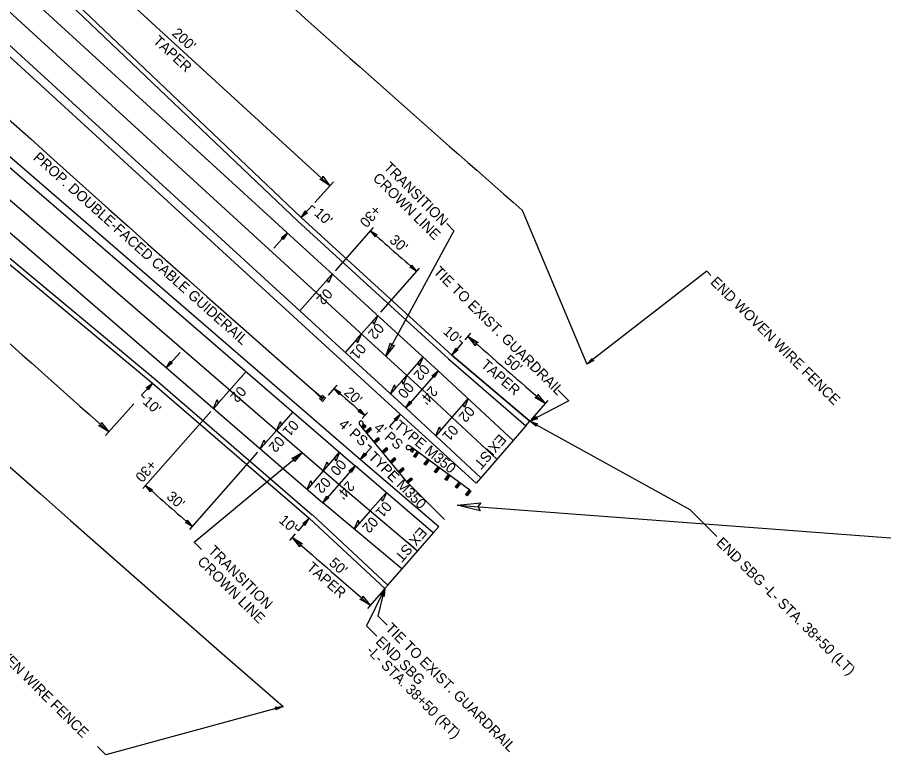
# Model space of a CAD drawing. Extents: x 1602193 to 1605074, y 908180 to 910630.
# Drawn here: x 1604022.9 to 1604444.5, y 908234.2 to 908593.2 of the extents above; entities that cross this region are included whole.
import ezdxf

# ---------------------------------------------------------------- set-up
doc = ezdxf.new("R2010")
doc.units = 0
for name, color, linetype in [('Prop Cable Guiderail Anchor Unit CELL', 7, 'Continuous'), ('Prop Cable Guiderail Double Face', 7, 'Continuous'), ('Prop Conc Shoulder Berm Gutter', 7, 'Continuous'), ('Prop Dimension', 7, 'Continuous'), ('Prop Dimension Text', 7, 'Continuous'), ('Prop DSN Text', 7, 'Continuous'), ('Prop EOT', 7, 'Continuous'), ('Prop Fence Woven Wire', 7, 'Continuous'), ('Prop Guardrail', 7, 'Continuous'), ('Prop Guardrail Anchor Unit CELL', 7, 'Continuous'), ('Prop Lane Lines', 7, 'Continuous'), ('Prop Paved Shoulder', 7, 'Continuous'), ('Prop Superelevation  Arrow CELL', 7, 'Continuous'), ('Prop Superelevation Label', 7, 'Continuous'), ('Prop Terminator CELL', 7, 'Continuous')]:
    doc.layers.add(name, color=color, linetype=linetype)

msp = doc.modelspace()

# ---------------------------------------------------------------- linework, layer by layer
at = {"layer": 'Prop Cable Guiderail Anchor Unit CELL'}
for p, q in [((1604153.38, 908423.5), (1604165.38, 908412.93)), ((1604165.38, 908412.93), (1604171.38, 908407.64)), ((1604165.38, 908412.93), (1604171.51, 908407.78)), ((1604165.38, 908412.93), (1604171.23, 908407.5)), ((1604165.38, 908412.93), (1604165.38, 908412.93)), ((1604171.29, 908409.05), (1604169.97, 908407.55)), ((1604171.47, 908406.23), (1604169.97, 908407.55)), ((1604171.47, 908408.12), (1604170.92, 908407.49)), ((1604171.3, 908407.16), (1604170.92, 908407.49)), ((1604172.8, 908407.73), (1604171.29, 908409.05)), ((1604171.85, 908407.78), (1604171.3, 908407.16)), ((1604171.85, 908407.78), (1604171.47, 908408.12)), ((1604172.8, 908407.73), (1604171.47, 908406.23))]:
    msp.add_line(p, q, dxfattribs=at)
at = {"layer": 'Prop Cable Guiderail Double Face'}
msp.add_arc((1613646.31, 919202), 14362.86, 225.366604, 228.628709, dxfattribs=at)
at = {"layer": 'Prop Conc Shoulder Berm Gutter'}
for p, q in [((1604016.5, 908633.39), (1604161.04, 908495.7)), ((1603934.31, 908543.23), (1604088.67, 908415.14)), ((1604161.04, 908495.7), (1604234.27, 908428.69)), ((1604234.27, 908428.69), (1604272.37, 908396.59)), ((1604088.67, 908415.14), (1604164.9, 908349.29)), ((1604270.42, 908394.34), (1604272.37, 908396.59)), ((1604164.9, 908349.29), (1604201.66, 908315.08)), ((1604201.66, 908315.08), (1604203.25, 908316.79))]:
    msp.add_line(p, q, dxfattribs=at)
at = {"layer": 'Prop Dimension'}
for p, q in [((1604027.95, 908645.82), (1604175.02, 908511.25)), ((1604176.72, 908513.15), (1604167.73, 908503.14)), ((1604161.04, 908495.7), (1604166.39, 908501.65)), ((1604196.08, 908490.81), (1604177.52, 908469.78)), ((1604231.84, 908492.85), (1604235.39, 908489.33)), ((1604147.68, 908480.82), (1604154.36, 908488.26)), ((1604235.39, 908489.33), (1604202.25, 908428.17)), ((1604218.48, 908471.09), (1604199.58, 908449.59)), ((1604240.85, 908436.22), (1604243.62, 908439.39)), ((1604234.46, 908428.9), (1604239.54, 908434.71)), ((1604095.35, 908422.58), (1604102.04, 908430.02)), ((1604227.69, 908421.16), (1604211.9, 908403.08)), ((1604083.32, 908409.19), (1604088.67, 908415.14)), ((1604178.34, 908414.05), (1604174.11, 908409.23)), ((1604281.1, 908406.65), (1604273.03, 908397.35)), ((1604079.55, 908404.99), (1604065.7, 908389.58)), ((1604117.03, 908401.22), (1604083.97, 908363.75)), ((1604193.37, 908400.87), (1604190.74, 908397.86)), ((1604209.26, 908400.06), (1604204, 908394.04)), ((1604139.8, 908381.54), (1604106.64, 908343.8)), ((1604108.99, 908337.66), (1604161.5, 908381.3)), ((1604187.27, 908374.89), (1604171.48, 908356.82)), ((1604159.64, 908343.26), (1604164.78, 908349.15)), ((1604155.46, 908338.48), (1604158.32, 908341.76)), ((1604112.55, 908334.14), (1604108.99, 908337.66)), ((1604201.01, 908314.33), (1604193.29, 908305.43))]:
    msp.add_line(p, q, dxfattribs=at)
for radius, start, end in [(14443.82, 227.66104, 228.45675), (14286.13, 228.578802, 228.698511), (14293.49, 228.858122, 229.057635), (14355.48, 228.728438, 228.808243), (14451.58, 228.578802, 228.698511), (14423.49, 228.858122, 229.057635)]:
    msp.add_arc((1613646.31, 919202), radius, start, end, dxfattribs=at)
at = {"layer": 'Prop Dimension Text'}
for p, q in [((1604166.39, 908501.65), (1604167.88, 908500.31)), ((1604238.03, 908436.03), (1604239.54, 908434.71)), ((1604083.32, 908409.19), (1604084.81, 908407.86)), ((1604204, 908394.04), (1604205.51, 908392.72)), ((1604193.66, 908385.24), (1604195.17, 908383.93)), ((1604195.17, 908383.93), (1604189.9, 908377.9)), ((1604158.13, 908344.58), (1604159.64, 908343.26))]:
    msp.add_line(p, q, dxfattribs=at)
at = {"layer": 'Prop DSN Text'}
for p, q in [((1604358.43, 908469.56), (1604300.01, 908424.29)), ((1604358.43, 908469.56), (1604360.47, 908467.54)), ((1604272.37, 908396.59), (1604350.11, 908353.55)), ((1604236.95, 908355.76), (1604508.97, 908335.15)), ((1604350.11, 908353.55), (1604363.29, 908340.51)), ((1604201.66, 908315.08), (1604192.77, 908296.9)), ((1604192.77, 908296.9), (1604197.84, 908291.88)), ((1604152.19, 908257.7), (1604065.86, 908234.2)), ((1604061.83, 908238.18), (1604065.86, 908234.2))]:
    msp.add_line(p, q, dxfattribs=at)
for points in [[(1604171.48, 908515.84), (1604175.02, 908511.25), (1604170.13, 908514.36), (1604171.32, 908514.63)], [(1604164.08, 908498.08), (1604161.04, 908495.7), (1604163.09, 908498.97), (1604163.27, 908498.18)], [(1604151.32, 908485.88), (1604154.36, 908488.26), (1604152.31, 908484.98), (1604152.13, 908485.78)], [(1604197.16, 908486.3), (1604194.75, 908489.31), (1604198.05, 908487.3), (1604197.25, 908487.1)], [(1604214.74, 908472.6), (1604217.16, 908469.59), (1604213.86, 908471.6), (1604214.65, 908471.79)], [(1604245.88, 908433.31), (1604242.25, 908437.82), (1604247.2, 908434.82), (1604246.01, 908434.53)], [(1604237.46, 908431.33), (1604234.46, 908428.9), (1604236.46, 908432.21), (1604236.65, 908431.42)], [(1604098.39, 908424.97), (1604095.35, 908422.58), (1604097.4, 908425.86), (1604097.58, 908425.06)], [(1604303.42, 908426.09), (1604300.01, 908424.29), (1604302.6, 908427.15), (1604302.64, 908426.33)], [(1604224.69, 908418.73), (1604227.69, 908421.16), (1604225.69, 908417.85), (1604225.5, 908418.64)], [(1604085.63, 908412.76), (1604088.67, 908415.14), (1604086.62, 908411.87), (1604086.44, 908412.66)], [(1604179.44, 908409.53), (1604177.02, 908412.54), (1604180.32, 908410.54), (1604179.53, 908410.34)], [(1604214.9, 908405.5), (1604211.9, 908403.08), (1604213.9, 908406.38), (1604214.09, 908405.59)], [(1604276.13, 908409.63), (1604279.79, 908405.14), (1604274.82, 908408.12), (1604276.01, 908408.41)], [(1604189.64, 908402.37), (1604192.06, 908399.36), (1604188.76, 908401.37), (1604189.55, 908401.56)], [(1604206.26, 908397.64), (1604209.26, 908400.06), (1604207.26, 908396.76), (1604207.07, 908397.55)], [(1604276.06, 908397.75), (1604272.37, 908396.59), (1604275.44, 908398.94), (1604275.33, 908398.13)], [(1604063.77, 908395.97), (1604067.38, 908391.44), (1604062.44, 908394.48), (1604063.63, 908394.76)], [(1604275.38, 908394.17), (1604272.37, 908396.59), (1604276.02, 908395.33), (1604275.29, 908394.98)], [(1604156.47, 908378.42), (1604161.5, 908381.3), (1604157.75, 908376.89), (1604157.65, 908378.1)], [(1604192.91, 908380.33), (1604189.9, 908377.9), (1604191.9, 908381.21), (1604192.1, 908380.42)], [(1604184.27, 908372.47), (1604187.27, 908374.89), (1604185.27, 908371.59), (1604185.08, 908372.38)], [(1604087.71, 908362.23), (1604085.3, 908365.25), (1604088.59, 908363.23), (1604087.8, 908363.04)], [(1604174.49, 908359.24), (1604171.48, 908356.82), (1604173.48, 908360.12), (1604173.68, 908359.33)], [(1604248.17, 908352.9), (1604236.95, 908355.76), (1604248.48, 908356.89), (1604246.93, 908355)], [(1604105.54, 908348.31), (1604107.96, 908345.3), (1604104.66, 908347.31), (1604105.45, 908347.5)], [(1604161.78, 908346.73), (1604164.78, 908349.15), (1604162.78, 908345.85), (1604162.59, 908346.64)], [(1604160.36, 908335.42), (1604156.72, 908339.92), (1604161.67, 908336.92), (1604160.49, 908336.63)], [(1604199.39, 908311.96), (1604201.66, 908315.08), (1604200.59, 908311.38), (1604200.2, 908312.09)], [(1604200.12, 908311.54), (1604201.66, 908315.08), (1604201.42, 908311.23), (1604200.88, 908311.84)], [(1604190.95, 908311.44), (1604194.6, 908306.94), (1604189.64, 908309.92), (1604190.82, 908310.22)], [(1604148.34, 908257.34), (1604152.19, 908257.7), (1604148.69, 908256.06), (1604148.97, 908256.82)]]:
    msp.add_lwpolyline(points, close=True, dxfattribs=at)
at = {"layer": 'Prop EOT'}
for p, q in [((1604007.07, 908623.04), (1604227.69, 908421.16)), ((1603990.88, 908605.32), (1604211.9, 908403.08)), ((1603959.9, 908571.31), (1604187.27, 908374.89)), ((1603943.97, 908553.36), (1604171.48, 908356.82)), ((1604264.18, 908387.15), (1604227.69, 908421.16)), ((1604248.45, 908369.01), (1604211.9, 908403.08)), ((1604264.18, 908387.15), (1604248.45, 908369.01)), ((1604225.27, 908342.29), (1604187.27, 908374.89)), ((1604209.93, 908324.61), (1604171.48, 908356.82)), ((1604225.27, 908342.29), (1604209.93, 908324.61))]:
    msp.add_line(p, q, dxfattribs=at)
at = {"layer": 'Prop Fence Woven Wire'}
msp.add_line((1604268.56, 908499.37), (1604300.01, 908424.29), dxfattribs=at)
for centre, radius, start, end in [((1613603.09, 919154.06), 14423.95, 224.073496, 229.063445), ((1613600.28, 919154.72), 14163.95, 227.268962, 228.788844)]:
    msp.add_arc(centre, radius, start, end, dxfattribs=at)
at = {"layer": 'Prop Guardrail'}
for p, q in [((1604161.04, 908495.7), (1604016.5, 908633.39)), ((1603934.31, 908543.23), (1604088.67, 908415.14)), ((1604234.27, 908428.69), (1604161.04, 908495.7)), ((1604272.37, 908396.59), (1604234.27, 908428.69)), ((1604088.67, 908415.14), (1604164.9, 908349.29)), ((1604230.85, 908348.73), (1604212.53, 908366.82)), ((1604164.9, 908349.29), (1604201.66, 908315.08))]:
    msp.add_line(p, q, dxfattribs=at)
at = {"layer": 'Prop Guardrail Anchor Unit CELL'}
for p, q in [((1604286.1, 908411.66), (1604291.37, 908406.45)), ((1604291.37, 908406.45), (1604272.37, 908396.59)), ((1604190.79, 908393.38), (1604189.4, 908395.08)), ((1604190.35, 908393.92), (1604191.6, 908394.95)), ((1604190.35, 908393.92), (1604190.9, 908394.37)), ((1604190.35, 908393.92), (1604190.9, 908394.37)), ((1604190.35, 908393.92), (1604192.49, 908393.86)), ((1604190.79, 908393.38), (1604191.43, 908393.91)), ((1604191.13, 908395.47), (1604190.9, 908394.37)), ((1604191.24, 908392.84), (1604191.6, 908394.95)), ((1604192.49, 908393.86), (1604191.24, 908392.84)), ((1604191.6, 908394.95), (1604192.49, 908393.86)), ((1604212.53, 908366.82), (1604190.79, 908393.38)), ((1604192.26, 908391.59), (1604194.54, 908393.45)), ((1604194.06, 908391.76), (1604192.26, 908391.59)), ((1604192.58, 908391.2), (1604193.16, 908391.68)), ((1604192.9, 908390.82), (1604195.17, 908392.68)), ((1604192.9, 908390.82), (1604193.42, 908392.54)), ((1604193.42, 908392.54), (1604195.17, 908392.68)), ((1604194.06, 908391.76), (1604193.42, 908392.54)), ((1604194.54, 908393.45), (1604194.06, 908391.76)), ((1604195.17, 908392.68), (1604194.54, 908393.45)), ((1604196.25, 908386.71), (1604198.53, 908388.57)), ((1604198.05, 908386.89), (1604196.25, 908386.71)), ((1604196.89, 908385.94), (1604199.16, 908387.8)), ((1604196.89, 908385.94), (1604197.41, 908387.66)), ((1604197.41, 908387.66), (1604199.16, 908387.8)), ((1604198.05, 908386.89), (1604197.41, 908387.66)), ((1604198.53, 908388.57), (1604198.05, 908386.89)), ((1604199.16, 908387.8), (1604198.53, 908388.57)), ((1604200.24, 908381.84), (1604202.52, 908383.7)), ((1604202.04, 908382.01), (1604200.24, 908381.84)), ((1604200.87, 908381.06), (1604203.15, 908382.92)), ((1604200.87, 908381.06), (1604201.4, 908382.79)), ((1604201.4, 908382.79), (1604203.15, 908382.92)), ((1604202.04, 908382.01), (1604201.4, 908382.79)), ((1604202.52, 908383.7), (1604202.04, 908382.01)), ((1604203.15, 908382.92), (1604202.52, 908383.7)), ((1604213.46, 908382.84), (1604214.54, 908383.13)), ((1604215.52, 908383.28), (1604213.76, 908384.58)), ((1604214.96, 908383.7), (1604214, 908382.4)), ((1604216.09, 908382.87), (1604214, 908382.4)), ((1604214, 908382.4), (1604215.13, 908381.57)), ((1604214.96, 908383.7), (1604214.54, 908383.13)), ((1604214.96, 908383.7), (1604214.54, 908383.13)), ((1604214.96, 908383.7), (1604215.13, 908381.57)), ((1604215.52, 908383.28), (1604215.03, 908382.62)), ((1604215.13, 908381.57), (1604216.09, 908382.87)), ((1604243.16, 908362.92), (1604215.52, 908383.28)), ((1604217.4, 908381.9), (1604215.65, 908379.53)), ((1604218.2, 908381.31), (1604216.46, 908378.94)), ((1604218.2, 908381.31), (1604216.51, 908380.69)), ((1604217.31, 908380.1), (1604217.4, 908381.9)), ((1604217.8, 908381.6), (1604217.36, 908381)), ((1604204.23, 908376.96), (1604206.5, 908378.82)), ((1604206.02, 908377.14), (1604204.23, 908376.96)), ((1604204.86, 908376.19), (1604207.14, 908378.05)), ((1604204.86, 908376.19), (1604205.39, 908377.91)), ((1604205.39, 908377.91), (1604207.14, 908378.05)), ((1604206.02, 908377.14), (1604205.39, 908377.91)), ((1604206.5, 908378.82), (1604206.02, 908377.14)), ((1604207.14, 908378.05), (1604206.5, 908378.82)), ((1604215.65, 908379.53), (1604217.31, 908380.1)), ((1604216.46, 908378.94), (1604215.65, 908379.53)), ((1604216.51, 908380.69), (1604216.46, 908378.94)), ((1604217.31, 908380.1), (1604216.51, 908380.69)), ((1604222.47, 908378.16), (1604220.73, 908375.8)), ((1604223.27, 908377.57), (1604221.53, 908375.2)), ((1604221.58, 908376.95), (1604221.53, 908375.2)), ((1604223.27, 908377.57), (1604221.58, 908376.95)), ((1604222.39, 908376.36), (1604221.58, 908376.95)), ((1604222.39, 908376.36), (1604222.47, 908378.16)), ((1604208.22, 908372.09), (1604210.49, 908373.95)), ((1604208.85, 908371.31), (1604211.13, 908373.17)), ((1604208.85, 908371.31), (1604209.38, 908373.04)), ((1604209.38, 908373.04), (1604211.13, 908373.17)), ((1604210.01, 908372.26), (1604209.38, 908373.04)), ((1604210.49, 908373.95), (1604210.01, 908372.26)), ((1604211.13, 908373.17), (1604210.49, 908373.95)), ((1604220.73, 908375.8), (1604222.39, 908376.36)), ((1604221.53, 908375.2), (1604220.73, 908375.8)), ((1604227.54, 908374.42), (1604225.8, 908372.06)), ((1604225.8, 908372.06), (1604227.46, 908372.62)), ((1604228.35, 908373.83), (1604226.6, 908371.47)), ((1604226.65, 908373.22), (1604226.6, 908371.47)), ((1604228.35, 908373.83), (1604226.65, 908373.22)), ((1604227.46, 908372.62), (1604226.65, 908373.22)), ((1604227.46, 908372.62), (1604227.54, 908374.42)), ((1604210.01, 908372.26), (1604208.22, 908372.09)), ((1604212.21, 908367.21), (1604214.48, 908369.07)), ((1604212.84, 908366.44), (1604215.12, 908368.3)), ((1604213.37, 908368.16), (1604215.12, 908368.3)), ((1604214.48, 908369.07), (1604214, 908367.39)), ((1604215.12, 908368.3), (1604214.48, 908369.07)), ((1604226.6, 908371.47), (1604225.8, 908372.06)), ((1604232.61, 908370.69), (1604230.87, 908368.32)), ((1604230.87, 908368.32), (1604232.53, 908368.89)), ((1604231.68, 908367.73), (1604230.87, 908368.32)), ((1604233.42, 908370.09), (1604231.68, 908367.73)), ((1604231.72, 908369.48), (1604231.68, 908367.73)), ((1604233.42, 908370.09), (1604231.72, 908369.48)), ((1604232.53, 908368.89), (1604231.72, 908369.48)), ((1604232.53, 908368.89), (1604232.61, 908370.69)), ((1604214, 908367.39), (1604212.21, 908367.21)), ((1604212.84, 908366.44), (1604213.37, 908368.16)), ((1604214, 908367.39), (1604213.37, 908368.16)), ((1604237.68, 908366.95), (1604235.94, 908364.59)), ((1604235.94, 908364.59), (1604237.6, 908365.15)), ((1604236.75, 908363.99), (1604235.94, 908364.59)), ((1604238.49, 908366.36), (1604236.75, 908363.99)), ((1604236.79, 908365.74), (1604236.75, 908363.99)), ((1604238.49, 908366.36), (1604236.79, 908365.74)), ((1604237.6, 908365.15), (1604236.79, 908365.74)), ((1604237.6, 908365.15), (1604237.68, 908366.95)), ((1604242.76, 908363.21), (1604241.01, 908360.85)), ((1604241.01, 908360.85), (1604242.67, 908361.41)), ((1604241.82, 908360.26), (1604241.01, 908360.85)), ((1604243.56, 908362.62), (1604241.82, 908360.26)), ((1604241.87, 908362), (1604241.82, 908360.26)), ((1604243.56, 908362.62), (1604241.87, 908362)), ((1604242.67, 908361.41), (1604241.87, 908362)), ((1604242.67, 908361.41), (1604242.76, 908363.21)), ((1604198.42, 908301.64), (1604201.66, 908315.08)), ((1604202.92, 908297.19), (1604198.42, 908301.64))]:
    msp.add_line(p, q, dxfattribs=at)
for centre, major_axis, start_param, end_param in [((1604190.17, 908395.71), (-0.769, -0.629), 2.210226, 6.283185), ((1604213.17, 908383.78), (-0.589, -0.799), 3.141593, 7.214552)]:
    msp.add_ellipse(centre, major_axis=major_axis, ratio=0.995379, start_param=start_param, end_param=end_param, dxfattribs=at)
at = {"layer": 'Prop Lane Lines'}
for p, q in [((1603998.97, 908614.19), (1604219.79, 908412.12)), ((1603951.82, 908562.44), (1604179.38, 908365.85)), ((1604219.79, 908412.12), (1604256.31, 908378.08)), ((1604179.38, 908365.85), (1604217.6, 908333.45))]:
    msp.add_line(p, q, dxfattribs=at)
at = {"layer": 'Prop Paved Shoulder'}
for p, q in [((1604014.91, 908631.68), (1604159.45, 908493.99)), ((1603988.19, 908602.36), (1604209.26, 908400.06)), ((1603962.56, 908574.31), (1604189.9, 908377.9)), ((1603935.84, 908544.99), (1604090.18, 908416.92)), ((1604159.45, 908493.99), (1604232.7, 908426.97)), ((1604232.7, 908426.97), (1604270.42, 908394.34)), ((1604090.18, 908416.92), (1604166.43, 908351.05)), ((1604209.26, 908400.06), (1604246.13, 908366.34)), ((1604270.42, 908394.34), (1604264.18, 908387.15)), ((1604189.9, 908377.9), (1604227.94, 908345.37)), ((1604248.45, 908369.01), (1604246.13, 908366.34)), ((1604166.49, 908350.99), (1604203.25, 908316.79)), ((1604227.94, 908345.37), (1604225.27, 908342.29)), ((1604209.93, 908324.61), (1604203.09, 908316.73))]:
    msp.add_line(p, q, dxfattribs=at)
at = {"layer": 'Prop Superelevation  Arrow CELL'}
for p, q in [((1604176.2, 908468.28), (1604160.32, 908450.28)), ((1604198.26, 908448.08), (1604190.34, 908439.07)), ((1604190.34, 908439.07), (1604182.42, 908430.05)), ((1604220.33, 908427.89), (1604212.43, 908418.85)), ((1604134.23, 908420.71), (1604118.35, 908402.72)), ((1604212.43, 908418.85), (1604204.53, 908409.82)), ((1604242.28, 908407.55), (1604234.4, 908398.5)), ((1604156.96, 908401.07), (1604149.04, 908392.06)), ((1604234.4, 908398.5), (1604226.52, 908389.45)), ((1604149.04, 908392.06), (1604141.12, 908383.04)), ((1604179.69, 908381.44), (1604171.79, 908372.41)), ((1604171.79, 908372.41), (1604163.89, 908363.37)), ((1604202.47, 908361.85), (1604194.66, 908352.89)), ((1604194.66, 908352.89), (1604186.86, 908343.93))]:
    msp.add_line(p, q, dxfattribs=at)
for points in [[(1604176.2, 908468.28), (1604174.34, 908463.91), (1604173.9, 908465.68)], [(1604198.26, 908448.08), (1604196.42, 908443.71), (1604195.97, 908445.48)], [(1604190.34, 908439.07), (1604188.5, 908434.7), (1604188.05, 908436.46)], [(1604220.33, 908427.89), (1604218.5, 908423.51), (1604218.05, 908425.28)], [(1604212.43, 908418.85), (1604210.6, 908414.48), (1604210.15, 908416.24)], [(1604204.53, 908409.82), (1604206.36, 908414.2), (1604206.81, 908412.43)], [(1604118.35, 908402.72), (1604120.2, 908407.08), (1604120.65, 908405.32)], [(1604242.28, 908407.55), (1604240.46, 908403.17), (1604240.01, 908404.94)], [(1604149.04, 908392.06), (1604150.89, 908396.43), (1604151.33, 908394.67)], [(1604226.52, 908389.45), (1604228.34, 908393.83), (1604228.79, 908392.07)], [(1604141.12, 908383.04), (1604142.97, 908387.42), (1604143.41, 908385.65)], [(1604179.69, 908381.44), (1604177.86, 908377.06), (1604177.41, 908378.83)], [(1604179.69, 908381.44), (1604177.86, 908377.06), (1604177.41, 908378.83)], [(1604171.79, 908372.41), (1604173.63, 908376.78), (1604174.08, 908375.02)], [(1604171.79, 908372.41), (1604173.63, 908376.78), (1604174.08, 908375.02)], [(1604163.89, 908363.37), (1604165.73, 908367.75), (1604166.18, 908365.98)], [(1604202.47, 908361.85), (1604200.65, 908357.47), (1604200.19, 908359.24)], [(1604186.86, 908343.93), (1604188.68, 908348.31), (1604189.14, 908346.55)]]:
    msp.add_lwpolyline(points, close=True, dxfattribs=at)
at = {"layer": 'Prop Terminator CELL'}
msp.add_lwpolyline([(1604206.48, 908433.56), (1604202.25, 908428.17), (1604204.42, 908434.71), (1604205.07, 908433.38)], close=True, dxfattribs=at)

# ---------------------------------------------------------------- texts
at = {"layer": 'Prop Cable Guiderail Double Face'}
msp.add_text('PROP. DOUBLE-FACED CABLE GUIDERAIL', height=5, rotation=318.3125, dxfattribs=at).set_placement((1604030.25, 908524.31))
at = {"layer": 'Prop Dimension'}
for s, rotation, p in [('TRANSITION', 315.2976, (1604200.81, 908519.82)), ('CROWN LINE', 315.2976, (1604195.54, 908514.49)), ('+30', 228.5788, (1604196.63, 908502.23)), ("30'", 318.639, (1604203.6, 908484.18)), ('+30', 228.5788, (1604087.42, 908378.18)), ("30'", 318.6433, (1604095.09, 908359.28)), ('TRANSITION', 315.2976, (1604115.39, 908333.09)), ('CROWN LINE', 315.2976, (1604110.11, 908327.76))]:
    msp.add_text(s, height=5, rotation=rotation, dxfattribs=at).set_placement(p)
at = {"layer": 'Prop Dimension Text'}
for s, rotation, p in [("200'", 317.5398, (1604097.79, 908584.91)), ('TAPER', 317.5398, (1604088.54, 908581.16)), ("10'", 318.0601, (1604167.02, 908497.28)), ("10'", 318.8581, (1604229.7, 908439.67)), ("50'", 318.9617, (1604259.37, 908425.54)), ('TAPER', 318.9593, (1604248.13, 908423.38)), ("20'", 318.7682, (1604181.48, 908409.96)), ("24'", 228.8182, (1604224.23, 908414.04)), ("10'", 318.0601, (1604083.56, 908405.49)), ("4' PS", 318.8581, (1604178.89, 908394.39)), ("4' PS", 318.8581, (1604196, 908392.72)), ("24'", 228.8182, (1604183.8, 908367.87)), ("10'", 318.8581, (1604149.8, 908347.74)), ("50'", 318.9639, (1604174.2, 908326.9)), ('TAPER', 318.9627, (1604163.34, 908324.73))]:
    msp.add_text(s, height=5, rotation=rotation, dxfattribs=at).set_placement(p)
at = {"layer": 'Prop DSN Text'}
for s, p in [('END WOVEN WIRE FENCE', (1604359.85, 908463.93)), ('END SBG -L- STA. 38+50 (LT)', (1604362.68, 908336.98)), ('END WOVEN WIRE FENCE', (1603994.18, 908301.87)), ('END SBG', (1604196.86, 908288.86)), ('-L- STA. 38+50 (RT)', (1604192.4, 908284.35))]:
    msp.add_text(s, height=5, rotation=315.2976, dxfattribs=at).set_placement(p)
at = {"layer": 'Prop Guardrail Anchor Unit CELL'}
for s, rotation, p in [('TIE TO EXIST. GUARDRAIL', 315.2976, (1604225.05, 908468.94)), ('TYPE M350', 320.7251, (1604205.81, 908393.63)), ('TYPE M350', 315.2976, (1604193.29, 908378.77)), ('TIE TO EXIST. GUARDRAIL', 315.2976, (1604201.68, 908295.28))]:
    msp.add_text(s, height=5, rotation=rotation, dxfattribs=at).set_placement(p)
at = {"layer": 'Prop Superelevation Label'}
for s, rotation, p in [('02', 228.5788, (1604172.99, 908461.62)), ('02', 228.6985, (1604198.06, 908444.82)), ('01', 228.6985, (1604189.32, 908434.87)), ('02', 228.8182, (1604220.25, 908424.75)), ('00', 228.8182, (1604212.59, 908416)), ('02', 228.5788, (1604131.03, 908414.06)), ('02', 228.9379, (1604242.19, 908404.4)), ('01', 228.6985, (1604156.54, 908397.56)), ('01', 228.9379, (1604234.19, 908395.22)), ('EXIST', 229.0576, (1604257.54, 908390.68)), ('02', 228.6985, (1604149.66, 908389.73)), ('00', 228.8182, (1604179.71, 908378.42)), ('02', 228.8182, (1604172.17, 908369.8)), ('01', 228.9379, (1604201.77, 908358)), ('02', 228.9379, (1604195.22, 908350.49)), ('EXIST', 229.0576, (1604218.96, 908345.38))]:
    msp.add_text(s, height=5, rotation=rotation, dxfattribs=at).set_placement(p)

doc.saveas('drawing.dxf')
